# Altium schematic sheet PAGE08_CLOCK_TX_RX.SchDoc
size 381 x 381 mm; SheetNumber: 9; SheetTotal: 28
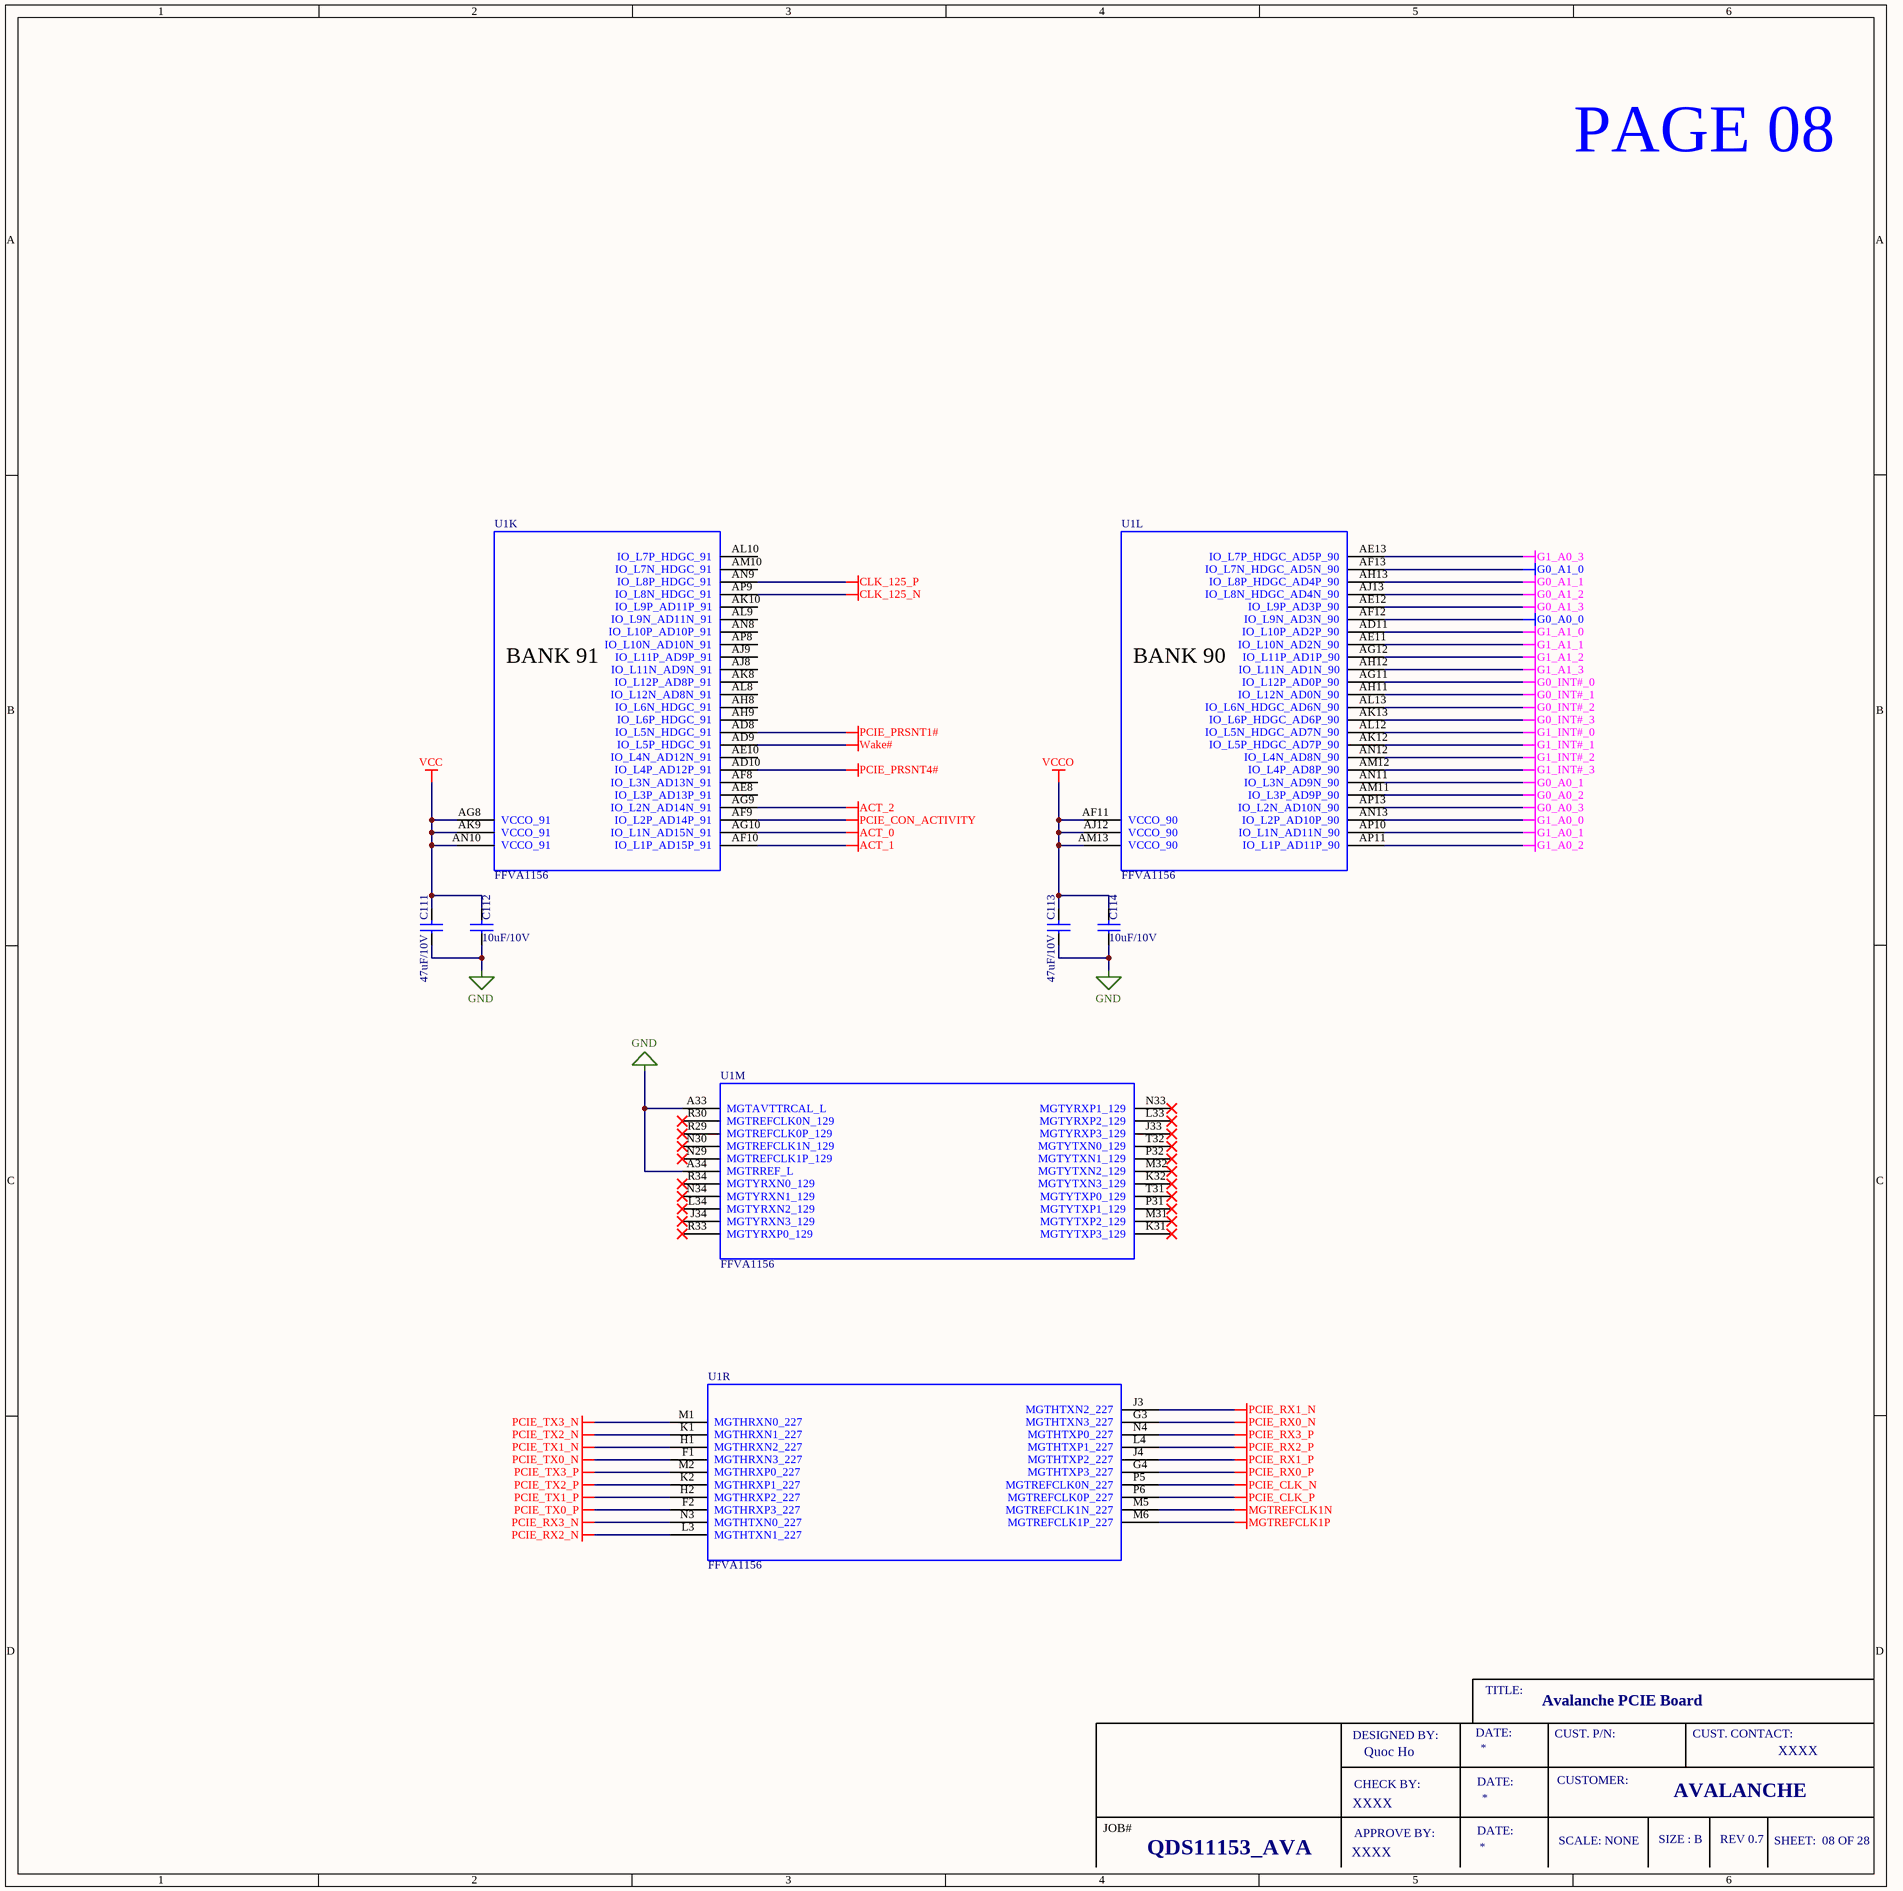
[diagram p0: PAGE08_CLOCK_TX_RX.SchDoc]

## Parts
C111  47uF/10V  [CN_0805]
C112  10uF/10V  [CN_0402]
C113  47uF/10V  [CN_0805]
C114  10uF/10V  [CN_0402]
U1  FFVA1156  [FFVA1156]  (parts K,L,M,R of 25)

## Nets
ACT_0: U1.AG10(IO_L1N_AD15N_91)
ACT_1: U1.AF10(IO_L1P_AD15P_91)
ACT_2: U1.AG9(IO_L2N_AD14N_91)
CLK_125_N: U1.AP9(IO_L8N_HDGC_91)
CLK_125_P: U1.AN9(IO_L8P_HDGC_91)
G0_A0_0: U1.AF12(IO_L9N_AD3N_90)
G0_A0_1: U1.AN11(IO_L3N_AD9N_90)
G0_A0_2: U1.AM11(IO_L3P_AD9P_90)
G0_A0_3: U1.AP13(IO_L2N_AD10N_90)
G0_A1_0: U1.AF13(IO_L7N_HDGC_AD5N_90)
G0_A1_1: U1.AH13(IO_L8P_HDGC_AD4P_90)
G0_A1_2: U1.AJ13(IO_L8N_HDGC_AD4N_90)
G0_A1_3: U1.AE12(IO_L9P_AD3P_90)
G0_INT#_0: U1.AG11(IO_L12P_AD0P_90)
G0_INT#_1: U1.AH11(IO_L12N_AD0N_90)
G0_INT#_2: U1.AL13(IO_L6N_HDGC_AD6N_90)
G0_INT#_3: U1.AK13(IO_L6P_HDGC_AD6P_90)
G1_A0_0: U1.AN13(IO_L2P_AD10P_90)
G1_A0_1: U1.AP10(IO_L1N_AD11N_90)
G1_A0_2: U1.AP11(IO_L1P_AD11P_90)
G1_A0_3: U1.AE13(IO_L7P_HDGC_AD5P_90)
G1_A1_0: U1.AD11(IO_L10P_AD2P_90)
G1_A1_1: U1.AE11(IO_L10N_AD2N_90)
G1_A1_2: U1.AG12(IO_L11P_AD1P_90)
G1_A1_3: U1.AH12(IO_L11N_AD1N_90)
G1_INT#_0: U1.AL12(IO_L5N_HDGC_AD7N_90)
G1_INT#_1: U1.AK12(IO_L5P_HDGC_AD7P_90)
G1_INT#_2: U1.AN12(IO_L4N_AD8N_90)
G1_INT#_3: U1.AM12(IO_L4P_AD8P_90)
GND: C111.1 C112.1 C113.1 C114.1 U1.A33(MGTAVTTRCAL_L) U1.A34(MGTRREF_L)
MGTREFCLK1N: U1.M5(MGTREFCLK1N_227)
MGTREFCLK1P: U1.M6(MGTREFCLK1P_227)
PCIE_CLK_N: U1.P5(MGTREFCLK0N_227)
PCIE_CLK_P: U1.P6(MGTREFCLK0P_227)
PCIE_CON_ACTIVITY: U1.AF9(IO_L2P_AD14P_91)
PCIE_PRSNT1#: U1.AD8(IO_L5N_HDGC_91)
PCIE_PRSNT4#: U1.AD10(IO_L4P_AD12P_91)
PCIE_RX0_N: U1.G3(MGTHTXN3_227)
PCIE_RX0_P: U1.G4(MGTHTXP3_227)
PCIE_RX1_N: U1.J3(MGTHTXN2_227)
PCIE_RX1_P: U1.J4(MGTHTXP2_227)
PCIE_RX2_N: U1.L3(MGTHTXN1_227)
PCIE_RX2_P: U1.L4(MGTHTXP1_227)
PCIE_RX3_N: U1.N3(MGTHTXN0_227)
PCIE_RX3_P: U1.N4(MGTHTXP0_227)
PCIE_TX0_N: U1.F1(MGTHRXN3_227)
PCIE_TX0_P: U1.F2(MGTHRXP3_227)
PCIE_TX1_N: U1.H1(MGTHRXN2_227)
PCIE_TX1_P: U1.H2(MGTHRXP2_227)
PCIE_TX2_N: U1.K1(MGTHRXN1_227)
PCIE_TX2_P: U1.K2(MGTHRXP1_227)
PCIE_TX3_N: U1.M1(MGTHRXN0_227)
PCIE_TX3_P: U1.M2(MGTHRXP0_227)
VCC: C111.2 C112.2 U1.AG8(VCCO_91) U1.AK9(VCCO_91) U1.AN10(VCCO_91)
VCCO: C113.2 C114.2 U1.AF11(VCCO_90) U1.AJ12(VCCO_90) U1.AM13(VCCO_90)
Wake#: U1.AD9(IO_L5P_HDGC_91)

Not connected (* = marked no-connect by the designer): U1 AE8(IO_L3P_AD13P_91) AE10(IO_L4N_AD12N_91) AF8(IO_L3N_AD13N_91) AH8(IO_L6N_HDGC_91) AH9(IO_L6P_HDGC_91) AJ8(IO_L11N_AD9N_91) AJ9(IO_L11P_AD9P_91) AK8(IO_L12P_AD8P_91) AK10(IO_L9P_AD11P_91) AL8(IO_L12N_AD8N_91) AL9(IO_L9N_AD11N_91) AL10(IO_L7P_HDGC_91) AM10(IO_L7N_HDGC_91) AN8(IO_L10P_AD10P_91) AP8(IO_L10N_AD10N_91) J33(MGTYRXP3_129)* J34(MGTYRXN3_129)* K31(MGTYTXP3_129)* K32(MGTYTXN3_129)* L33(MGTYRXP2_129)* L34(MGTYRXN2_129)* M31(MGTYTXP2_129)* M32(MGTYTXN2_129)* N29(MGTREFCLK1P_129)* N30(MGTREFCLK1N_129)* N33(MGTYRXP1_129)* N34(MGTYRXN1_129)* P31(MGTYTXP1_129)* P32(MGTYTXN1_129)* R29(MGTREFCLK0P_129)* R30(MGTREFCLK0N_129)* R33(MGTYRXP0_129)* R34(MGTYRXN0_129)* T31(MGTYTXP0_129)* T32(MGTYTXN0_129)*

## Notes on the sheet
- PAGE 08
- (near U1) BANK 91
- (near U1) BANK 90
- TITLE:
- Avalanche PCIE Board
- DESIGNED BY:
- CHECK BY:
- Quoc Ho
- DATE:
- CUST. P/N:
- CUSTOMER:
- CUST. CONTACT:
- XXXX
- JOB#
- APPROVE BY:
- SCALE: NONE
- SIZE : B
- AVALANCHE
- REV 0.7
- SHEET:  08 OF 28
- QDS11153_AVA

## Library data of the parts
C111 C113 = CAP: CAP CER 47UF 10V X5R 0805; Manufacturer: Murata Electronics; Manufacturer Part Number: GRM21BR61A476ME15K
C112 C114 = CAP: CAP CER 10UF 10V X5R 0402; Manufacturer Part Number: GRM155R61A106ME11D; Manufacturer: Murata Electronics
U1 = FFVA1156: IC FPGA 516 I/O 1156FCBGA; Manufacturer: AMD; Manufacturer Part Number: XCKU15P-1FFVA1156E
